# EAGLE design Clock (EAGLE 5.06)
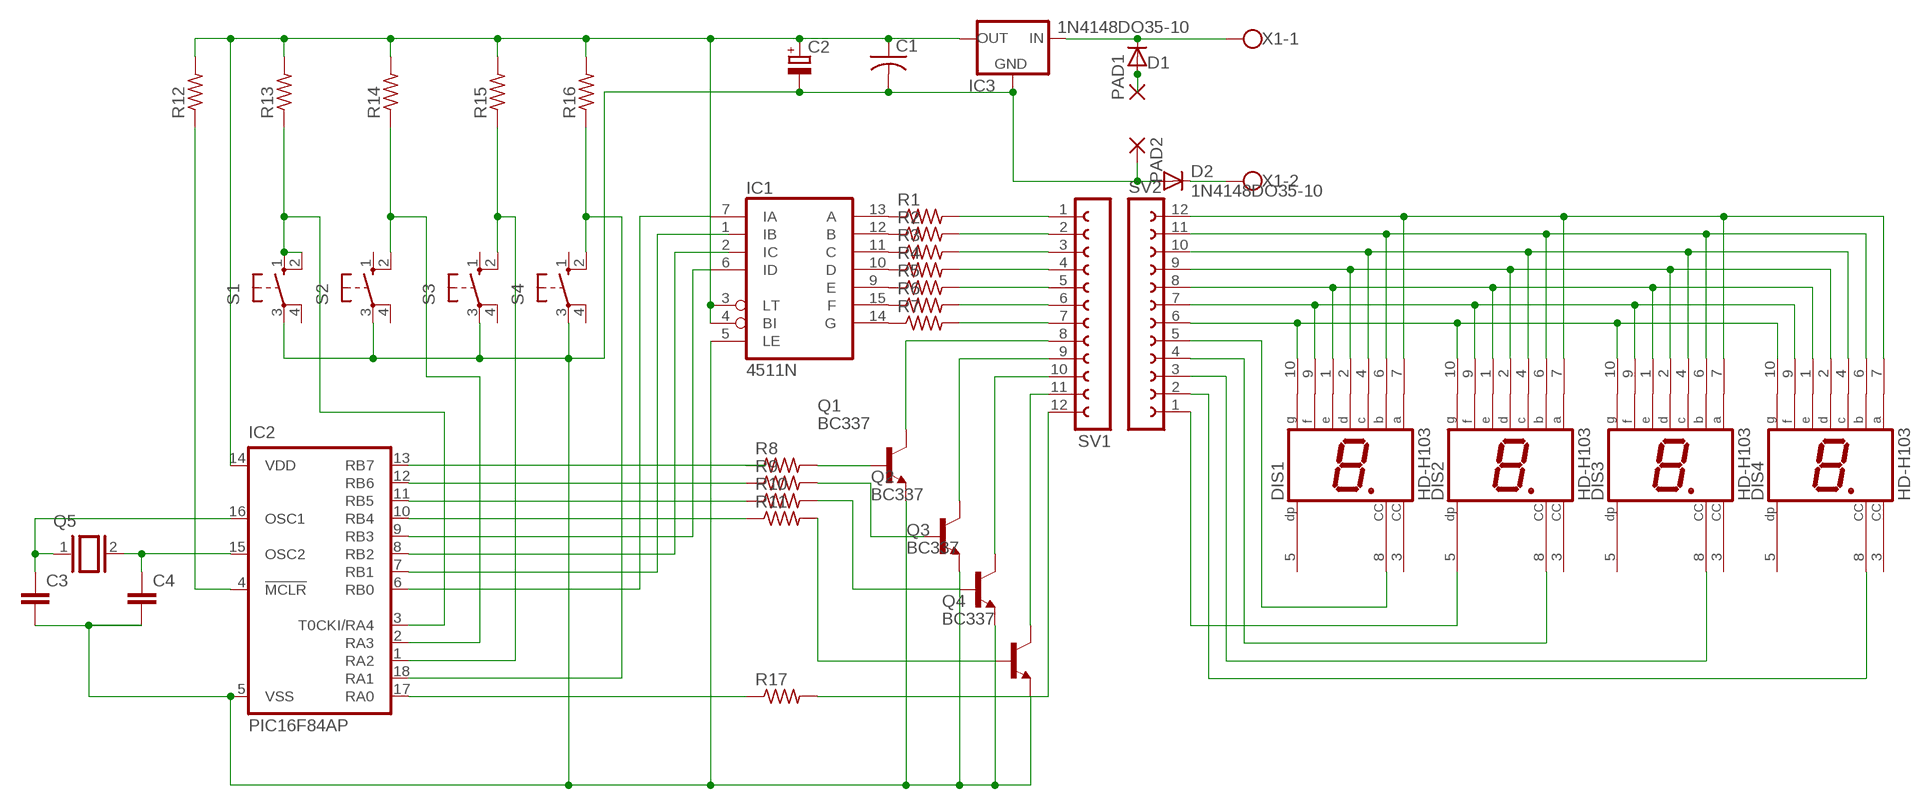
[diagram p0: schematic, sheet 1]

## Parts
C1  C-US050-025X075  [C050-025X075]
C2  CPOL-EUE5-8.5  [E5-8,5]
C3  C2.5/2  [C2.5-2]
C4  C2.5/2  [C2.5-2]
D1  1N4148DO35-10  [DO35-10]
D2  1N4148DO35-10  [DO35-10]
DIS1  HD-H103  [HDSP-M]
DIS2  HD-H103  [HDSP-M]
DIS3  HD-H103  [HDSP-M]
DIS4  HD-H103  [HDSP-M]
IC1  4511N  [DIL16]
IC2  PIC16F84AP  [DIL18]
IC3  78XXS  [78XXS]
PAD1  3,81/1,4  [3,81/1,4]
PAD2  3,81/1,4  [3,81/1,4]
Q1  BC337  [TO92]
Q2  BC337  [TO92]
Q3  BC337  [TO92]
Q4  BC337  [TO92]
Q5  XTAL/S  [QS]
R1  R-US_0207/10  [0207/10]
R2  R-US_0207/10  [0207/10]
R3  R-US_0207/10  [0207/10]
R4  R-US_0207/10  [0207/10]
R5  R-US_0207/10  [0207/10]
R6  R-US_0207/10  [0207/10]
R7  R-US_0207/10  [0207/10]
R8  R-US_0207/10  [0207/10]
R9  R-US_0207/10  [0207/10]
R10  R-US_0207/10  [0207/10]
R11  R-US_0207/10  [0207/10]
R12  R-US_0207/10  [0207/10]
R13  R-US_0207/10  [0207/10]
R14  R-US_0207/10  [0207/10]
R15  R-US_0207/10  [0207/10]
R16  R-US_0207/10  [0207/10]
R17  R-US_0207/10  [0207/10]
S1  10-XX  [B3F-10XX]
S2  10-XX  [B3F-10XX]
S3  10-XX  [B3F-10XX]
S4  10-XX  [B3F-10XX]
SV1  FE12-1  [FE12]
SV2  FE12-1  [FE12]
X1  W237-102  [W237-102]

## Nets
N$1: Q1.3(C) SV1.8
N$2: Q3.2(B) R10.2
N$3: Q3.3(C) SV1.10
N$4: IC2.11(RB5) R10.1
N$5: IC1.13(A) R1.1
N$6: IC1.12(B) R2.1
N$7: IC1.11(C) R3.1
N$8: IC1.10(D) R4.1
N$9: IC1.9(E) R5.1
N$10: IC1.15(F) R6.1
N$11: IC1.14(G) R7.1
N$12: Q1.2(B) R8.2
N$13: Q2.2(B) R9.2
N$14: Q4.3(C) SV1.11
N$16: DIS1.9(F) DIS2.9(F) DIS3.9(F) DIS4.9(F) SV2.7
N$17: DIS1.7(A) DIS2.7(A) DIS3.7(A) DIS4.7(A) SV2.12
N$18: DIS1.6(B) DIS2.6(B) DIS3.6(B) DIS4.6(B) SV2.11
N$19: DIS1.4(C) DIS2.4(C) DIS3.4(C) DIS4.4(C) SV2.10
N$20: DIS1.2(D) DIS2.2(D) DIS3.2(D) DIS4.2(D) SV2.9
N$21: DIS1.1(E) DIS2.1(E) DIS3.1(E) DIS4.1(E) SV2.8
N$22: DIS1.10(G) DIS2.10(G) DIS3.10(G) DIS4.10(G) SV2.6
N$23: R1.2 SV1.1
N$24: IC2.13(RB7)
N$25: IC2.12(RB6)
N$26: Q2.3(C) SV1.9
N$27: DIS4.8(CC) SV2.2
N$28: C1.1 C2.+ IC1.3(LT) IC1.4(BI) IC2.14(VDD) IC3.OUT R12.2 R13.2 R14.2 R15.2 R16.2
N$29: IC1.7(IA) IC2.6(RB0)
N$30: IC2.7(RB1)
N$31: IC2.8(RB2)
N$32: IC1.6(ID) IC2.9(RB3)
N$33: Q4.2(B) R11.2
N$34: C1.2 C2.- C3.2 C4.2 D2.A IC1.5(LE) IC2.5(VSS) IC3.GND PAD2.1(P) Q1.1(E) Q2.1(E) Q3.1(E) Q4.1(E) S1.3(P) S2.3(P) S3.3(P) S4.3(P)
N$35: D1.C IC3.IN X1.1
N$36: D1.A PAD1.1(P)
N$37: D2.C X1.2
N$38: IC2.17(RA0) R17.1
N$39: IC2.4(!MCLR) R12.1
N$40: IC2.3(T0CKI/RA4) R13.1 S1.1(S) S1.2(S1)
N$41: IC2.2(RA3) R14.1 S2.2(S1)
N$42: IC2.1(RA2) R15.1 S3.2(S1)
N$43: IC2.18(RA1) R16.1 S4.2(S1)
N$44: DIS2.5(DP) SV2.1
N$45: C4.1 IC2.15(OSC2) Q5.2
N$46: C3.1 IC2.16(OSC1) Q5.1
N$47: R2.2 SV1.2
N$48: R3.2 SV1.3
N$49: R4.2 SV1.4
N$50: R5.2 SV1.5
N$51: R6.2 SV1.6
N$52: R7.2 SV1.7
N$53: DIS1.8(CC) SV2.5
N$54: DIS2.8(CC) SV2.4
N$55: DIS3.8(CC) SV2.3
N$56: IC2.10(RB4) R11.1
N$57: R17.2 SV1.12
Unconnected: DIS1.3(CC) DIS1.5(DP) DIS2.3(CC) DIS3.3(CC) DIS3.5(DP) DIS4.3(CC) DIS4.5(DP) IC1.1(IB) IC1.2(IC) R8.1 R9.1 S1.4(P1) S2.1(S) S2.4(P1) S3.1(S) S3.4(P1) S4.1(S) S4.4(P1)

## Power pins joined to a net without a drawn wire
VDD: IC1.16(VDD)
VSS: IC1.8(VSS)

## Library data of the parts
C1 = resistor:C-US: CAPACITOR, American symbol
C2 = resistor:CPOL-EU: POLARIZED CAPACITOR, European symbol
C3 C4 = capacitor-wima:C: CAPACITOR
D1 D2 = diode:1N4148: DIODE
DIS1-DIS4 = display-hp:HD-H103: LED DISPLAY 1-character 7 segment, decimal point right
IC1 = 45xx:4511: BCD to 7-segment LATCH/DECODER/DRIVER
IC2 = microchip:PIC16F8*: MICROCONTROLLER 8-Bit PIC16F8X Family - CMOS Flash/EEPROM Pin Compatible : PIC16F83, PIC16CR83, PIC16F84A, PIC16CR84 see also PIC16C*
IC3 = v-reg:78XXS: VOLTAGE REGULATOR
PAD1 PAD2 = wirepad:3,81/1,4: THROUGH-HOLE PAD
Q1-Q4 = transistor-npn:BC337*: NPN Transistor
Q5 = special:XTAL/S: CRYSTAL
R1-R17 = resistor:R-US_: RESISTOR, American symbol
S1-S4 = switch-omron:10-XX: OMRON SWITCH
SV1 SV2 = con-lsta:FE12-1: FEMALE HEADER
X1 = con-wago-500:W237-102: WAGO SCREW CLAMP

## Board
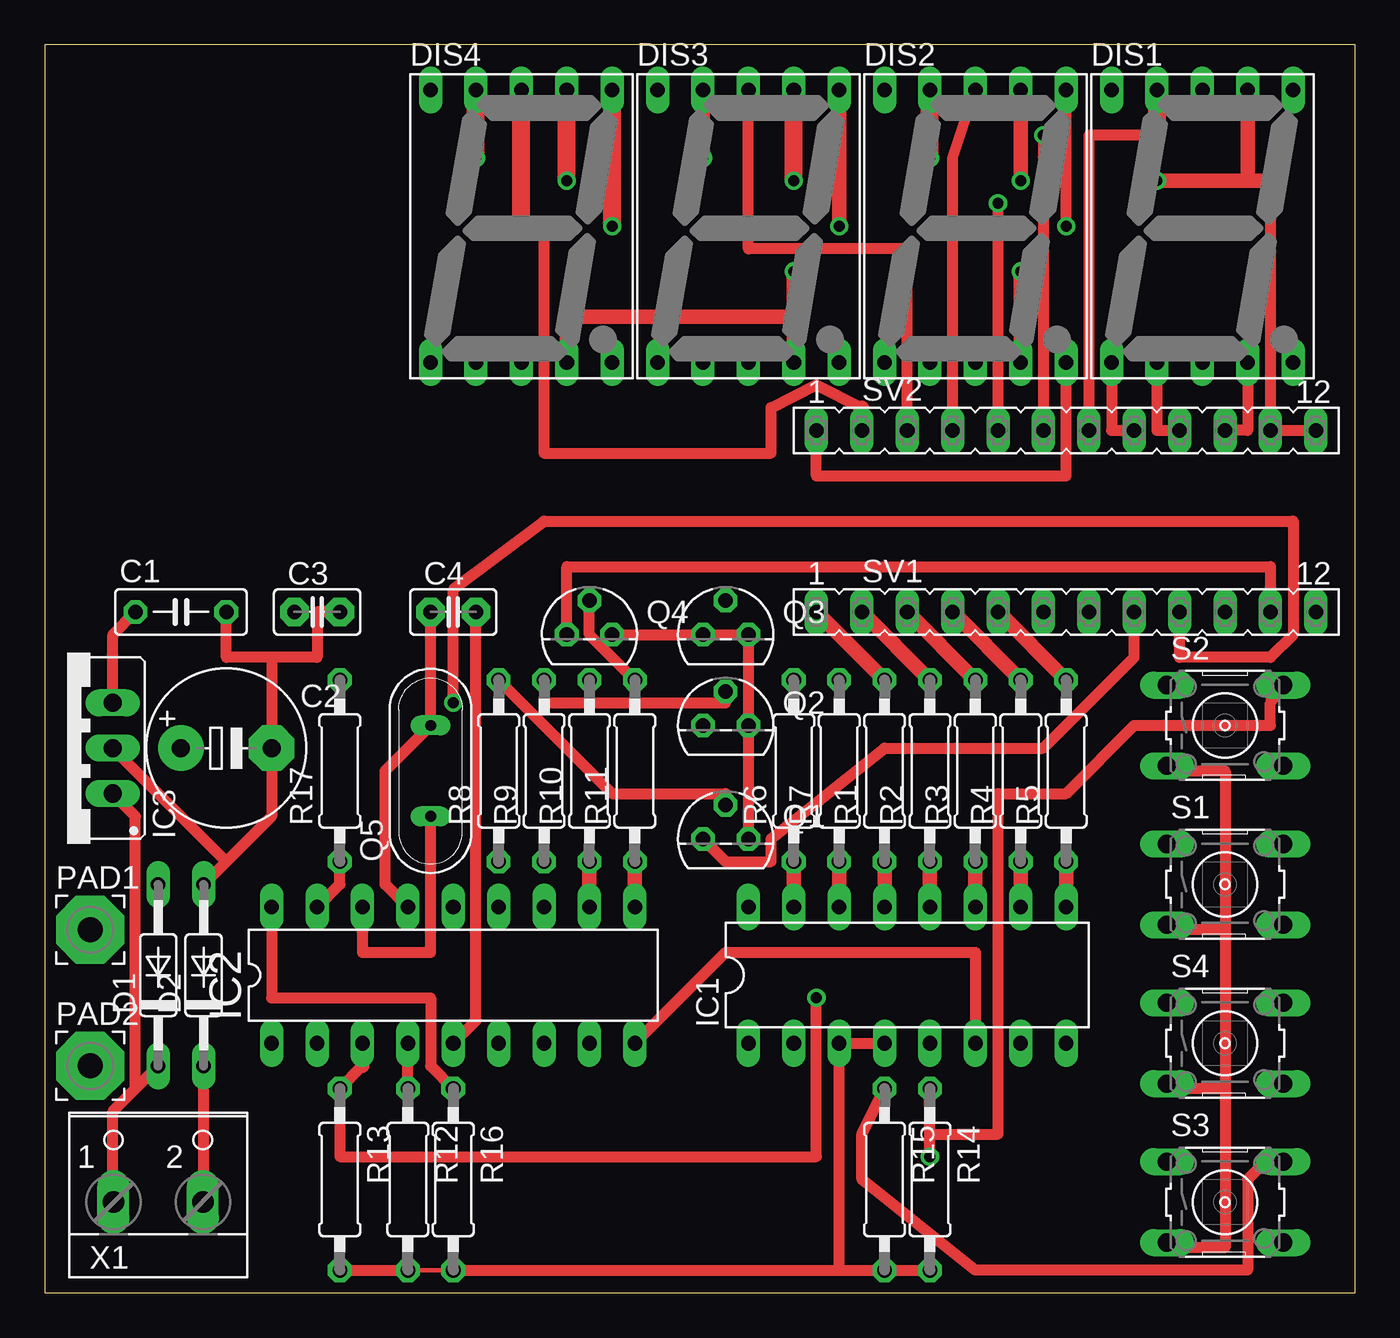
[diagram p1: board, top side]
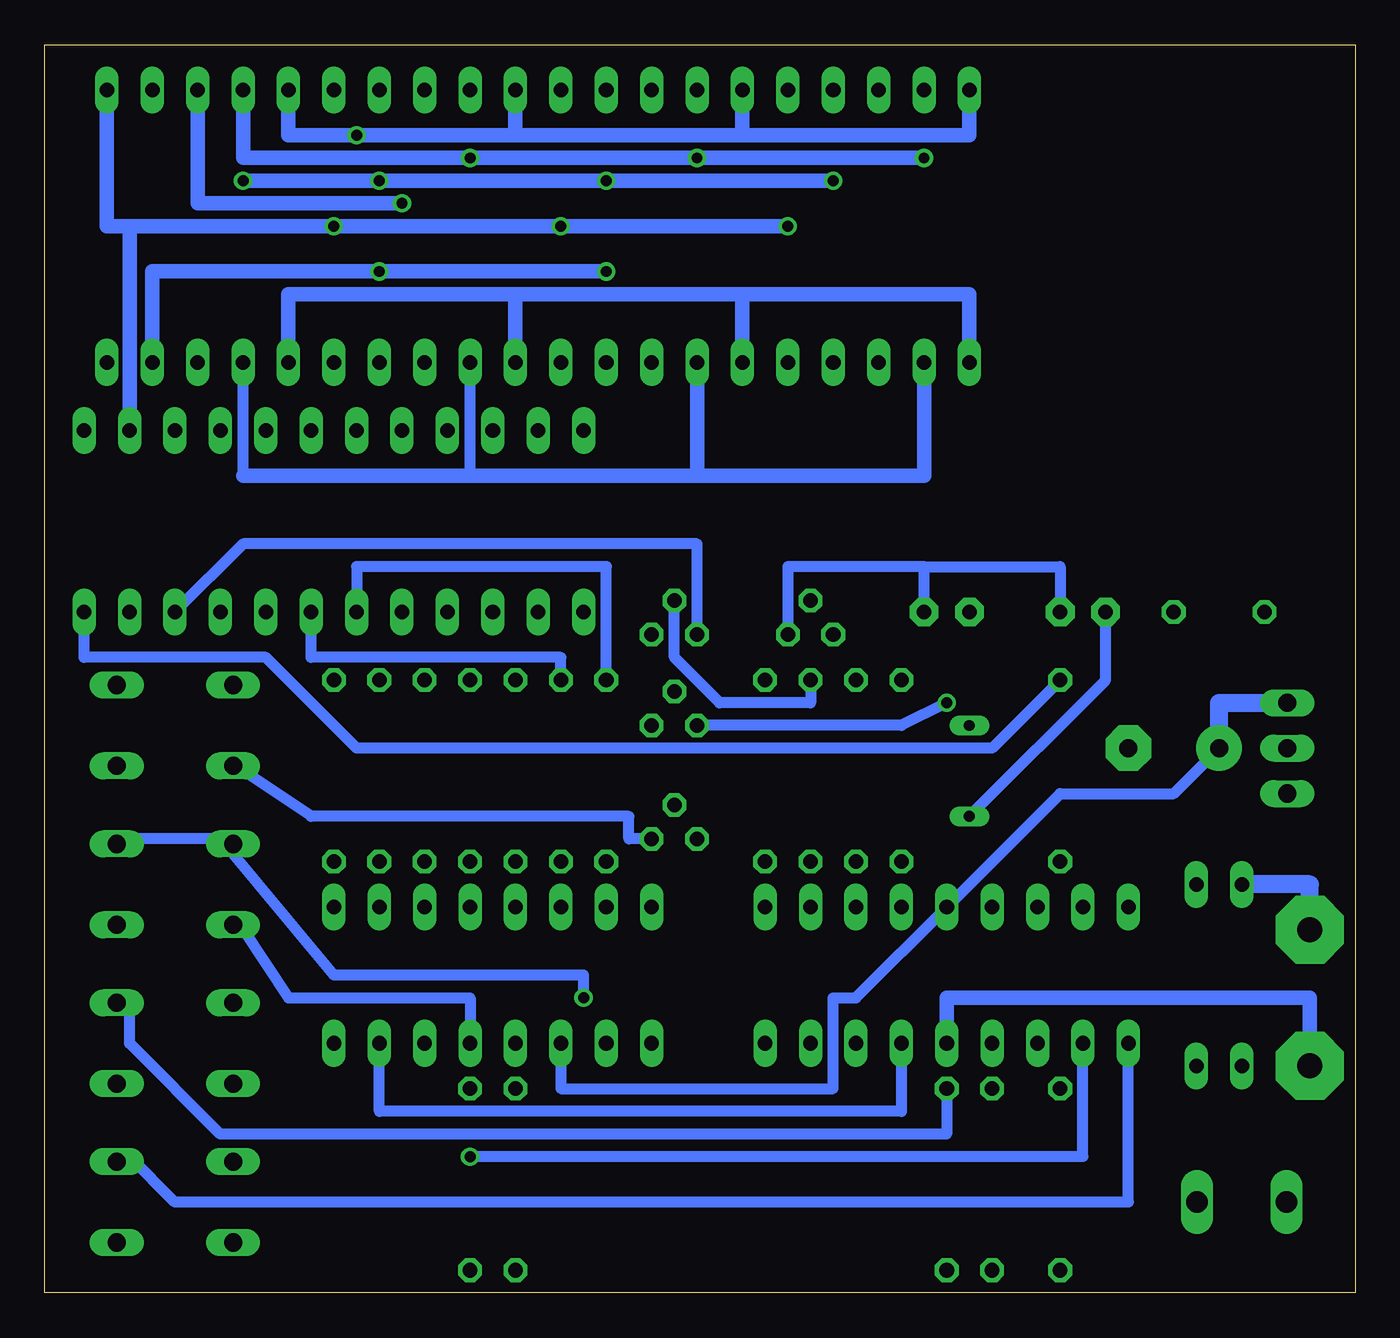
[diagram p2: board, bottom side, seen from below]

Size 73.33 x 69.84 mm. Coordinates in mm from the lower left corner, seen from the top.
Outline: 0,0 73.33,0 73.33,69.84 0,69.84 0,0
Copper layers (1*16): Top 0.035mm / dielectric 1.5mm / Bottom 0.035mm
Design rules "default": minimum track width 10mil, minimum drill 24mil, track to track 8mil, track to pad 8mil, pad to pad 8mil, via to via 8mil, smd to smd 8mil, copper to edge 40mil, drill to drill 8mil, minimum pad ring 10mil, minimum via ring 8mil, stop-mask expansion 4mil, vias tented up to drill 0mil, thermal gap 10mil

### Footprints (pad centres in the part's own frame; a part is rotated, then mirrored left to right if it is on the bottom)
C050-025X075 = drill 0.813 octagon: 1 -2.54,0; 2 2.54,0
E5-8,5 = drill 1.016 pad 2.54 round: + -2.54,0 | drill 1.016 pad 2.54 octagon: - 2.54,0
C2.5-2 = drill 0.813 pad 1.6 octagon: 1 -1.27,0; 2 1.27,0
DO35-10 = drill 0.813 long: A 5.08,0; C -5.08,0
HDSP-M = drill 0.813 long: 1 -5.08,-7.62; 2 -2.54,-7.62; 3 0,-7.62; 4 2.54,-7.62; 5 5.08,-7.62; 6 5.08,7.62; 7 2.54,7.62; 8 0,7.62; 9 -2.54,7.62; 10 -5.08,7.62
DIL16 = drill 0.813 long: 1 -8.89,-3.81; 2 -6.35,-3.81; 3 -3.81,-3.81; 4 -1.27,-3.81; 5 1.27,-3.81; 6 3.81,-3.81; 7 6.35,-3.81; 8 8.89,-3.81; 9 8.89,3.81; 10 6.35,3.81; 11 3.81,3.81; 12 1.27,3.81; 13 -1.27,3.81; 14 -3.81,3.81; 15 -6.35,3.81; 16 -8.89,3.81
DIL18 = drill 0.813 long: 1 -10.16,-3.81; 2 -7.62,-3.81; 3 -5.08,-3.81; 4 -2.54,-3.81; 5 0,-3.81; 6 2.54,-3.81; 7 5.08,-3.81; 8 7.62,-3.81; 9 10.16,-3.81; 10 10.16,3.81; 11 7.62,3.81; 12 5.08,3.81; 13 2.54,3.81; 14 0,3.81; 15 -2.54,3.81; 16 -5.08,3.81; 17 -7.62,3.81; 18 -10.16,3.81
78XXS = drill 1.016 long: GND 0,-2.54; IN -2.54,-2.54; OUT 2.54,-2.54
3,81/1,4 = drill 1.397 pad 3.81 octagon: 1 0,0
TO92 = drill 0.813 octagon: 1 1.27,0; 2 0,1.905; 3 -1.27,0
QS = drill 0.61 long: 1 -2.54,0; 2 2.54,0
0207/10 = drill 0.813 octagon: 1 -5.08,0; 2 5.08,0
B3F-10XX = drill 1.016 long: 1 -3.251,2.261; 2 3.251,2.261; 3 -3.251,-2.261; 4 3.251,-2.261
FE12 = drill 0.813 long: 1 -13.97,0; 2 -11.43,0; 3 -8.89,0; 4 -6.35,0; 5 -3.81,0; 6 -1.27,0; 7 1.27,0; 8 3.81,0; 9 6.35,0; 10 8.89,0; 11 11.43,0; 12 13.97,0
W237-102 = drill 1.194 long: 1 -2.5,-1.27; 2 2.5,-1.27

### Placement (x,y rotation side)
C1  7.62,38.1 0 top
C2  10.16,30.48 0 top
C3  15.24,38.1 0 top
C4  22.86,38.1 0 top
D1  6.35,17.78 90 top
D2  8.89,17.78 90 top
DIS1  64.77,59.69 0 top
DIS2  52.07,59.69 0 top
DIS3  39.37,59.69 0 top
DIS4  26.67,59.69 0 top
IC1  48.26,17.78 0 top
IC2  22.86,17.78 0 top
IC3  1.27,30.48 90 top
PAD1  2.54,20.32 0 top
PAD2  2.54,12.7 0 top
Q1  38.1,25.4 0 top
Q2  38.1,31.75 0 top
Q3  38.1,36.83 0 top
Q4  30.48,36.83 0 top
Q5  21.59,29.21 90 top
R1  46.99,29.21 90 top
R2  49.53,29.21 90 top
R3  52.07,29.21 90 top
R4  54.61,29.21 90 top
R5  57.15,29.21 90 top
R6  41.91,29.21 90 top
R7  44.45,29.21 90 top
R8  25.4,29.21 90 top
R9  27.94,29.21 90 top
R10  30.48,29.21 90 top
R11  33.02,29.21 90 top
R12  20.32,6.35 270 top
R13  16.51,6.35 270 top
R14  49.53,6.35 270 top
R15  46.99,6.35 270 top
R16  22.86,6.35 270 top
R17  16.51,29.21 90 top
S1  66.04,22.86 0 top
S2  66.04,31.75 0 top
S3  66.04,5.08 0 top
S4  66.04,13.97 0 top
SV1  57.15,38.1 0 top
SV2  57.15,48.26 0 top
X1  6.35,6.35 0 top

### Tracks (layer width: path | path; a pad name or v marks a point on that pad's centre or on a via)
N$1
  Top 0.61: Q1.3 38.1,24.13 40.64,24.13 40.64,25.4 46.99,30.48 55.88,30.48 60.96,35.56 SV1.8
N$2
  Bottom 0.61: R10.2 30.48,33.02 35.56,33.02 38.1,35.56 Q3.2
N$3
  Bottom 0.61: Q3.3 36.83,41.91 62.23,41.91 SV1.10
N$4
  Top 0.813: IC2.11 R10.1
N$5
  Top 0.813: IC1.13 R1.1
N$6
  Top 0.813: IC1.12 R2.1
N$7
  Top 0.813: IC1.11 R3.1
N$8
  Top 0.813: IC1.10 R4.1
N$9
  Top 0.813: IC1.9 R5.1
N$10
  Top 0.813: IC1.15 R6.1
N$11
  Top 0.813: IC1.14 R7.1
N$12
  Top 0.254: 38.1,27.94 Q1.2
  Top 0.61: R8.2 31.75,27.94 38.1,27.94
N$13
  Top 0.61: R9.2 27.94,33.02 38.1,33.02 Q2.2
N$14
  Top 0.61: Q4.3 29.21,40.64 68.58,40.64 SV1.11
N$16  (via drill 0.61)
  Top 0.61: SV2.7 58.42,64.77 62.23,64.77
  Top 0.813: v36.83,63.5 DIS3.9
  Top 1.016: v24.13,63.5 DIS4.9 | v49.53,63.5 DIS2.9 | DIS1.9 62.23,64.77
  Bottom 0.813: v24.13,63.5 v36.83,63.5 v49.53,63.5 62.23,63.5 DIS1.9
N$17  (via drill 0.61)
  Top 0.61: SV2.12 68.58,48.26 68.58,62.23
  Top 0.813: 67.31,62.23 DIS1.7 | v54.61,62.23 DIS2.7 | v62.23,62.23 67.31,62.23 | 67.31,62.23 68.58,62.23
  Top 1.016: v29.21,62.23 DIS4.7 | v41.91,62.23 DIS3.7
  Bottom 0.813: v29.21,62.23 v41.91,62.23 v54.61,62.23 v62.23,62.23
N$18  (via drill 0.61)
  Top 0.61: v57.15,59.69 DIS2.6
  Top 0.813: v44.45,59.69 DIS3.6
  Top 1.016: v31.75,59.69 DIS4.6
  Bottom 0.813: 68.58,59.69 v57.15,59.69 v44.45,59.69 v31.75,59.69 | DIS1.6 69.85,59.69 68.58,59.69 | 68.58,59.69 SV2.11
N$19  (via drill 0.61)
  Top 0.254: 41.91,54.61 DIS3.4
  Top 0.61: SV2.10 67.31,48.26 DIS1.4
  Top 0.813: DIS4.4 29.21,54.61 41.91,54.61 | v54.61,57.15 DIS2.4 | DIS3.4 v41.91,57.15
  Bottom 0.813: DIS1.4 67.31,57.15 v54.61,57.15 v41.91,57.15
N$20
  Top 0.61: SV2.9 62.23,48.26 DIS1.2
  Bottom 0.61: 49.53,45.72 DIS2.2 | 62.23,45.72 DIS1.2
  Bottom 0.813: DIS4.2 24.13,45.72 36.83,45.72 | 36.83,45.72 DIS3.2 | 36.83,45.72 49.53,45.72 62.23,45.72
N$21
  Top 0.61: SV2.8 59.69,48.26 DIS1.1
  Bottom 0.813: DIS4.1 21.59,55.88 34.29,55.88 | 34.29,55.88 DIS3.1 | 46.99,55.88 DIS2.1 | 34.29,55.88 46.99,55.88 | 46.99,55.88 59.69,55.88 DIS1.1
N$22  (via drill 0.61)
  Top 0.61: v55.88,64.77 SV2.6
  Bottom 0.813: DIS4.10 21.59,64.77 34.29,64.77 | 34.29,64.77 DIS3.10 | 46.99,64.77 DIS2.10 | 34.29,64.77 46.99,64.77 | 46.99,64.77 v55.88,64.77 59.69,64.77 DIS1.10
N$23
  Top 0.813: R1.2 SV1.1
N$26  (via drill 0.61)
  Top 0.61: v22.86,33.02 22.86,39.37 27.94,43.18 69.85,43.18 69.85,36.83 68.58,35.56 63.5,35.56 SV1.9
  Bottom 0.61: Q2.3 25.4,31.75 v22.86,33.02
N$27
  Top 0.61: 45.72,49.53 43.18,50.8 40.64,49.53 40.64,46.99 27.94,46.99 27.94,59.69
  Top 0.813: 45.72,49.53 SV2.2 | 27.94,59.69 26.67,59.69
  Top 1.016: 26.67,59.69 DIS4.8
N$28
  Top 0.254: R12.2 R16.2
  Top 0.61: C1.1 3.81,36.83 IC3.OUT | R13.2 R12.2 | IC1.4 IC1.3 44.45,1.27 | R14.2 R15.2 44.45,1.27 | R16.2 44.45,1.27
  Bottom 0.61: C2.+ 10.16,27.94 16.51,27.94 IC2.14 27.94,16.51 29.21,16.51 29.21,11.43 44.45,11.43 IC1.3
  Bottom 1.016: C2.+ 7.62,33.02 IC3.OUT
N$29
  Bottom 0.61: IC2.6 25.4,10.16 54.61,10.16 IC1.7
N$32
  Top 0.61: IC2.9 38.1,19.05 52.07,19.05 IC1.6
N$33
  Top 0.61: R11.2 30.48,36.83 Q4.2
N$34
  Top 0.61: 66.04,11.43 66.04,2.54 63.5,2.54 S3.3 | 66.04,11.43 63.5,11.43 S4.3 | 66.04,20.32 66.04,11.43 | 66.04,20.32 66.04,29.21 63.5,29.21 S2.3 | 66.04,20.32 63.5,20.32 S1.3 | 10.16,24.13 12.7,26.67 C2.- 12.7,35.56 | 10.16,24.13 D2.A | 12.7,35.56 10.16,35.56 C1.2 | 10.16,24.13 IC3.GND | C3.2 15.24,38.1 15.24,35.56 12.7,35.56 | Q1.1 Q2.1 Q3.1 Q4.1 | IC2.5 24.13,15.24 C4.2
  Bottom 0.254: S1.3 62.23,20.32
  Bottom 0.406: 62.23,29.21 S2.3
  Bottom 0.61: IC1.5 49.53,16.51 59.69,16.51 62.23,20.32 | 24.13,40.64 31.75,40.64 Q4.1 | C4.2 24.13,40.64 | C3.2 16.51,40.64 24.13,40.64 | 62.23,29.21 58.42,26.67 40.64,26.67 40.64,25.4 Q1.1
  Bottom 0.813: PAD2.1 2.54,16.51 22.86,16.51 IC2.5
N$35
  Top 0.254: X1.1 3.81,5.08
  Top 0.61: 5.08,11.43 3.81,10.16 3.81,5.08 | 5.08,11.43 D1.C | IC3.IN 5.08,26.67 5.08,11.43
N$36
  Bottom 1.016: D1.A 2.54,22.86 PAD1.1
N$37
  Top 0.254: X1.2 8.89,5.08
  Top 0.61: 8.89,5.08 D2.C
N$38
  Top 0.61: IC2.17 16.51,22.86 R17.1
N$39
  Top 0.61: R12.1 IC2.4
N$40  (via drill 0.61)
  Top 0.61: 17.78,12.7 R13.1 16.51,7.62 43.18,7.62 v43.18,16.51
  Top 0.813: 17.78,12.7 IC2.3
  Bottom 0.254: 69.85,25.4 S1.2 | 63.5,25.4 S1.1
  Bottom 0.61: 69.85,25.4 63.5,25.4 57.15,17.78 43.18,17.78 v43.18,16.51
N$41  (via drill 0.61)
  Top 0.61: v49.53,7.62 49.53,8.89 | 49.53,8.89 R14.1 | 49.53,8.89 53.34,8.89 53.34,27.94 57.15,27.94 60.96,31.75 68.58,31.75 68.58,33.02 S2.2
  Bottom 0.61: IC2.2 15.24,7.62 v49.53,7.62
N$42
  Top 0.254: S3.2 68.58,7.62
  Top 0.61: R15.1 45.72,8.89 45.72,6.35 52.07,1.27 67.31,1.27 67.31,6.35 68.58,7.62
  Bottom 0.254: 68.58,7.62 S3.2
  Bottom 0.61: IC2.1 12.7,5.08 66.04,5.08 68.58,7.62
N$43
  Top 0.61: IC2.18 12.7,16.51 21.59,16.51 21.59,12.7 R16.1
  Bottom 0.254: 68.58,16.51 S4.2
  Bottom 0.61: 68.58,16.51 68.58,13.97 63.5,8.89 22.86,8.89 R16.1
N$44
  Top 0.61: SV2.1 43.18,45.72 57.15,45.72 DIS2.5
N$45
  Top 0.61: C4.1 Q5.2 19.05,29.21 19.05,22.86 IC2.15
N$46
  Top 0.61: IC2.16 17.78,19.05 21.59,19.05 Q5.1
  Bottom 0.61: Q5.1 13.97,34.29 C3.1
N$47
  Top 0.813: R2.2 SV1.2
N$48
  Top 0.813: R3.2 SV1.3
N$49
  Top 0.813: R4.2 SV1.4
N$50
  Top 0.813: R5.2 SV1.5
N$51
  Bottom 0.61: R6.2 41.91,40.64 55.88,40.64 SV1.6
N$52
  Bottom 0.61: R7.2 44.45,35.56 58.42,35.56 SV1.7
N$53  (via drill 0.61)
  Top 0.61: SV2.5 v53.34,60.96
  Bottom 0.813: v53.34,60.96 64.77,60.96 DIS1.8
N$54
  Top 0.61: SV2.4 50.8,63.5 DIS2.8
N$55
  Top 0.61: SV2.3 48.26,58.42 39.37,58.42 DIS3.8
N$56
  Top 0.813: IC2.10 R11.1
N$57
  Bottom 0.61: R17.2 20.32,30.48 55.88,30.48 60.96,35.56 71.12,35.56 SV1.12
